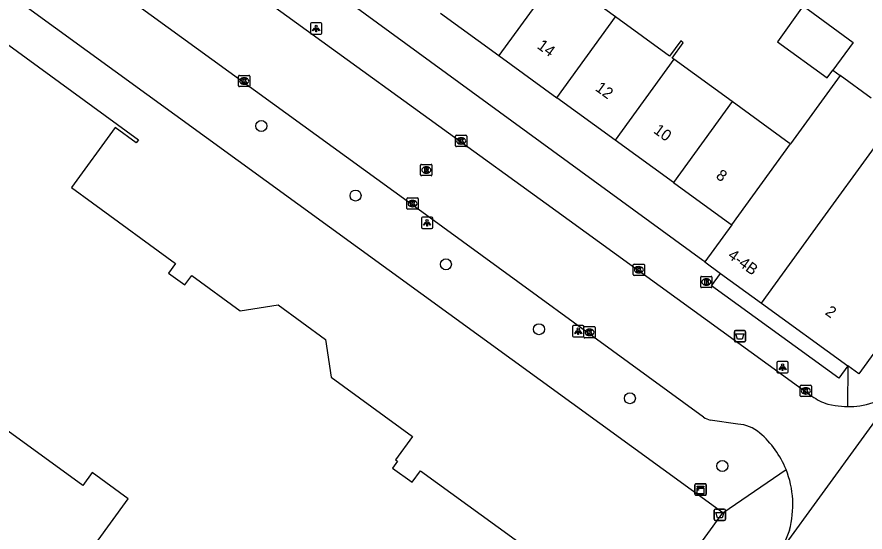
# Model space of a CAD drawing. Extents: x 159675 to 160530, y 382179 to 382901.
# Drawn here: x 160100.6 to 160175.7, y 382438.2 to 382483.9 of the extents above; entities that cross this region are included whole.
import ezdxf

# ---------------------------------------------------------------- set-up
doc = ezdxf.new("R2010")
doc.units = 0
for name, color, linetype in [('IMGEO_Afvalbak', 7, 'Continuous'), ('IMGEO_Boom', 7, 'Continuous'), ('IMGEO_Brandkraan', 7, 'Continuous'), ('IMGEO_Kast', 7, 'Continuous'), ('IMGEO_Kolk', 7, 'Continuous'), ('IMGEO_Lichtpunt', 7, 'Continuous'), ('IMGEO_Pand', 7, 'Continuous'), ('IMGEO_Pand_nummerreeks', 7, 'Continuous'), ('IMGEO_Rijbaan_lokaal_gesloten', 7, 'Continuous'), ('IMGEO_Rijbaan_lokaal_open', 7, 'Continuous'), ('IMGEO_Rioolput', 7, 'Continuous'), ('IMGEO_Voetpad_open', 7, 'Continuous')]:
    doc.layers.add(name, color=color, linetype=linetype)

msp = doc.modelspace()

# ---------------------------------------------------------------- linework, layer by layer
at = {"layer": 'IMGEO_Afvalbak'}
for p, q in [((160164.146, 382455.161), (160164.146, 382455.961)), ((160164.146, 382455.961), (160164.146, 382455.161)), ((160164.246, 382456.061), (160165.036, 382456.061)), ((160165.036, 382456.061), (160164.246, 382456.061)), ((160165.136, 382455.961), (160165.136, 382455.161)), ((160165.136, 382455.161), (160165.136, 382455.961)), ((160165.036, 382455.061), (160164.246, 382455.061)), ((160164.246, 382455.061), (160165.036, 382455.061)), ((160162.369, 382439.328), (160162.369, 382440.128)), ((160162.369, 382440.128), (160162.369, 382439.328)), ((160162.469, 382440.228), (160163.259, 382440.228)), ((160163.259, 382440.228), (160162.469, 382440.228)), ((160163.359, 382440.128), (160163.359, 382439.328)), ((160163.359, 382439.328), (160163.359, 382440.128)), ((160163.259, 382439.228), (160162.469, 382439.228)), ((160162.469, 382439.228), (160163.259, 382439.228))]:
    msp.add_line(p, q, dxfattribs=at)
for points in [[(160164.289, 382455.775), (160164.993, 382455.775), (160164.844, 382455.305), (160164.438, 382455.305), (160164.289, 382455.775)], [(160162.512, 382439.942), (160163.216, 382439.942), (160163.067, 382439.472), (160162.661, 382439.472), (160162.512, 382439.942)]]:
    msp.add_lwpolyline(points, dxfattribs=at)
for centre, start, end in [((160164.246, 382455.961), 90, 180), ((160164.246, 382455.961), 90, 180), ((160165.036, 382455.961), 0, 90), ((160165.036, 382455.961), 360, 90), ((160164.246, 382455.161), 180, 270), ((160164.246, 382455.161), 180, 270), ((160165.036, 382455.161), 270, 0), ((160165.036, 382455.161), 270, 0), ((160162.469, 382440.128), 90, 180), ((160162.469, 382440.128), 90, 180), ((160163.259, 382440.128), 0, 90), ((160163.259, 382440.128), 360, 90), ((160162.469, 382439.328), 180, 270), ((160162.469, 382439.328), 180, 270), ((160163.259, 382439.328), 270, 0), ((160163.259, 382439.328), 270, 0)]:
    msp.add_arc(centre, 0.1, start, end, dxfattribs=at)
at = {"layer": 'IMGEO_Boom'}
for centre in [(160122.222, 382474.208), (160130.572, 382468.037), (160138.58, 382461.94), (160146.827, 382456.187), (160154.885, 382450.065), (160163.082, 382444.058)]:
    msp.add_circle(centre, 0.489, dxfattribs=at)
at = {"layer": 'IMGEO_Brandkraan'}
for p, q in [((160161.163, 382459.947), (160161.163, 382460.799)), ((160161.238, 382460.873), (160162.09, 382460.873)), ((160161.651, 382460.653), (160161.676, 382460.653)), ((160162.164, 382460.799), (160162.164, 382459.947)), ((160162.09, 382459.873), (160161.238, 382459.873)), ((160161.674, 382460.093), (160161.649, 382460.093))]:
    msp.add_line(p, q, dxfattribs=at)
for points in [[(160161.163, 382459.947), (160161.163, 382460.799)], [(160161.238, 382460.873), (160162.09, 382460.873)], [(160161.511, 382460.573), (160161.511, 382460.173), (160161.724, 382460.173)], [(160161.742, 382460.573), (160161.511, 382460.573)], [(160161.69, 382460.492), (160161.636, 382460.492), (160161.636, 382460.416)], [(160161.636, 382460.416), (160161.689, 382460.416)], [(160162.164, 382460.799), (160162.164, 382459.947)], [(160162.09, 382459.873), (160161.238, 382459.873)], [(160161.698, 382460.34), (160161.636, 382460.34), (160161.636, 382460.259)], [(160161.636, 382460.259), (160161.698, 382460.259)]]:
    msp.add_lwpolyline(points, dxfattribs=at)
for centre, radius, start, end in [((160161.24, 382460.797), 0.0765, 91.55205, 178.44795), ((160161.24, 382460.797), 0.0765, 91.55205, 178.44795), ((160161.691, 382460.454), 0.0379, 267.82845, 90.93552), ((160161.746, 382460.428), 0.145, 59.4692, 91.53667), ((160161.771, 382460.475), 0.0922, 285.51372, 58.15012), ((160161.776, 382460.283), 0.105, 301.31148, 78.98903), ((160162.088, 382460.797), 0.0765, 1.55205, 88.44795), ((160162.088, 382460.797), 0.0765, 1.55205, 88.44795), ((160161.24, 382459.949), 0.0765, 181.55205, 268.44795), ((160161.24, 382459.949), 0.0765, 181.55205, 268.44795), ((160161.699, 382460.299), 0.0404, 269.87594, 90.50774), ((160161.73, 382460.424), 0.251, 268.66757, 293.53466), ((160162.088, 382459.949), 0.0765, 271.55205, 358.44795), ((160162.088, 382459.949), 0.0765, 271.55205, 358.44795)]:
    msp.add_arc(centre, radius, start, end, dxfattribs=at)
for centre, major_axis, ratio, start_param, end_param in [((160161.65, 382460.373), (-0.387, 0.002), 0.722429, 4.712389, 7.853982), ((160161.675, 382460.373), (-0.39, 0.002), 0.717154, 1.570796, 4.712389)]:
    msp.add_ellipse(centre, major_axis=major_axis, ratio=ratio, start_param=start_param, end_param=end_param, dxfattribs=at)
at = {"layer": 'IMGEO_Kast'}
for p, q in [((160160.658, 382441.551), (160160.658, 382442.392)), ((160160.658, 382442.392), (160160.658, 382441.551)), ((160160.733, 382442.476), (160161.574, 382442.476)), ((160161.574, 382442.476), (160160.733, 382442.476)), ((160161.658, 382442.401), (160161.658, 382441.56)), ((160161.658, 382441.56), (160161.658, 382442.401)), ((160161.583, 382441.476), (160160.742, 382441.476)), ((160160.742, 382441.476), (160161.583, 382441.476))]:
    msp.add_line(p, q, dxfattribs=at)
for points in [[(160160.853, 382442.266), (160161.453, 382442.266), (160161.453, 382442.181), (160160.853, 382442.181), (160160.853, 382442.266)], [(160160.853, 382442.091), (160161.453, 382442.091), (160161.453, 382441.602), (160160.853, 382441.602), (160160.853, 382442.091)]]:
    msp.add_lwpolyline(points, dxfattribs=at)
msp.add_circle((160160.937, 382441.94), 0.0377, dxfattribs=at)
for centre, start, end in [((160160.736, 382442.398), 92.4484, 184.28452), ((160160.736, 382442.398), 92.4484, 184.28452), ((160161.58, 382442.398), 2.4484, 94.28452), ((160161.58, 382442.398), 2.4484, 94.28452), ((160160.736, 382441.554), 182.4484, 274.28452), ((160160.736, 382441.554), 182.4484, 274.28452), ((160161.58, 382441.554), 272.4484, 4.28452), ((160161.58, 382441.554), 272.4484, 4.28452)]:
    msp.add_arc(centre, 0.0779, start, end, dxfattribs=at)
at = {"layer": 'IMGEO_Kolk'}
for p, q in [((160120.196, 382477.767), (160120.196, 382478.619)), ((160120.271, 382478.693), (160121.123, 382478.693)), ((160120.684, 382478.473), (160120.709, 382478.473)), ((160121.197, 382478.619), (160121.197, 382477.767)), ((160121.123, 382477.693), (160120.271, 382477.693)), ((160120.707, 382477.913), (160120.682, 382477.913)), ((160139.432, 382472.452), (160139.432, 382473.304)), ((160139.507, 382473.378), (160140.359, 382473.378)), ((160140.433, 382473.304), (160140.433, 382472.452)), ((160139.943, 382472.598), (160139.918, 382472.598)), ((160139.92, 382473.158), (160139.945, 382473.158)), ((160140.359, 382472.378), (160139.507, 382472.378)), ((160135.127, 382466.9), (160135.127, 382467.752)), ((160135.202, 382467.826), (160136.054, 382467.826)), ((160135.615, 382467.606), (160135.64, 382467.606)), ((160136.128, 382467.752), (160136.128, 382466.9)), ((160136.054, 382466.826), (160135.202, 382466.826)), ((160135.638, 382467.046), (160135.613, 382467.046)), ((160155.26, 382461.959), (160156.112, 382461.959)), ((160155.185, 382461.033), (160155.185, 382461.885)), ((160155.696, 382461.179), (160155.671, 382461.179)), ((160155.673, 382461.739), (160155.698, 382461.739)), ((160156.186, 382461.885), (160156.186, 382461.033)), ((160156.112, 382460.959), (160155.26, 382460.959)), ((160150.813, 382455.485), (160150.813, 382456.337)), ((160150.888, 382456.411), (160151.74, 382456.411)), ((160151.301, 382456.191), (160151.326, 382456.191)), ((160151.814, 382456.337), (160151.814, 382455.485)), ((160151.74, 382455.411), (160150.888, 382455.411)), ((160151.324, 382455.631), (160151.299, 382455.631)), ((160169.982, 382450.292), (160169.982, 382451.144)), ((160170.057, 382451.218), (160170.909, 382451.218)), ((160170.47, 382450.998), (160170.495, 382450.998)), ((160170.983, 382451.144), (160170.983, 382450.292)), ((160170.909, 382450.218), (160170.057, 382450.218)), ((160170.493, 382450.438), (160170.468, 382450.438))]:
    msp.add_line(p, q, dxfattribs=at)
for points in [[(160120.196, 382477.767), (160120.196, 382478.619)], [(160120.271, 382478.693), (160121.123, 382478.693)], [(160121.197, 382478.619), (160121.197, 382477.767)], [(160121.123, 382477.693), (160120.271, 382477.693)], [(160120.517, 382478.393), (160120.64, 382478.393), (160120.64, 382478.242), (160120.77, 382478.393), (160120.934, 382478.393), (160120.788, 382478.242), (160120.941, 382477.993), (160120.789, 382477.993), (160120.704, 382478.157), (160120.64, 382478.09), (160120.64, 382477.993), (160120.517, 382477.993), (160120.517, 382478.393)], [(160139.432, 382472.452), (160139.432, 382473.304)], [(160139.507, 382473.378), (160140.359, 382473.378)], [(160140.433, 382473.304), (160140.433, 382472.452)], [(160139.753, 382473.078), (160139.876, 382473.078), (160139.876, 382472.927), (160140.006, 382473.078), (160140.17, 382473.078), (160140.024, 382472.927), (160140.177, 382472.678), (160140.025, 382472.678), (160139.94, 382472.842), (160139.876, 382472.775), (160139.876, 382472.678), (160139.753, 382472.678), (160139.753, 382473.078)], [(160140.359, 382472.378), (160139.507, 382472.378)], [(160135.127, 382466.9), (160135.127, 382467.752)], [(160135.202, 382467.826), (160136.054, 382467.826)], [(160135.448, 382467.526), (160135.571, 382467.526), (160135.571, 382467.375), (160135.701, 382467.526), (160135.865, 382467.526), (160135.719, 382467.375), (160135.872, 382467.126), (160135.72, 382467.126), (160135.635, 382467.29), (160135.571, 382467.223), (160135.571, 382467.126), (160135.448, 382467.126), (160135.448, 382467.526)], [(160136.128, 382467.752), (160136.128, 382466.9)], [(160136.054, 382466.826), (160135.202, 382466.826)], [(160155.26, 382461.959), (160156.112, 382461.959)], [(160155.185, 382461.033), (160155.185, 382461.885)], [(160155.506, 382461.659), (160155.629, 382461.659), (160155.629, 382461.508), (160155.759, 382461.659), (160155.923, 382461.659), (160155.777, 382461.508), (160155.93, 382461.259), (160155.778, 382461.259), (160155.693, 382461.423), (160155.629, 382461.356), (160155.629, 382461.259), (160155.506, 382461.259), (160155.506, 382461.659)], [(160156.186, 382461.885), (160156.186, 382461.033)], [(160156.112, 382460.959), (160155.26, 382460.959)], [(160150.813, 382455.485), (160150.813, 382456.337)], [(160150.888, 382456.411), (160151.74, 382456.411)], [(160151.134, 382456.111), (160151.257, 382456.111), (160151.257, 382455.96), (160151.387, 382456.111), (160151.551, 382456.111), (160151.405, 382455.96), (160151.558, 382455.711), (160151.406, 382455.711), (160151.321, 382455.875), (160151.257, 382455.808), (160151.257, 382455.711), (160151.134, 382455.711), (160151.134, 382456.111)], [(160151.814, 382456.337), (160151.814, 382455.485)], [(160151.74, 382455.411), (160150.888, 382455.411)], [(160169.982, 382450.292), (160169.982, 382451.144)], [(160170.057, 382451.218), (160170.909, 382451.218)], [(160170.303, 382450.918), (160170.426, 382450.918), (160170.426, 382450.767), (160170.556, 382450.918), (160170.72, 382450.918), (160170.574, 382450.767), (160170.727, 382450.518), (160170.575, 382450.518), (160170.49, 382450.682), (160170.426, 382450.615), (160170.426, 382450.518), (160170.303, 382450.518), (160170.303, 382450.918)], [(160170.983, 382451.144), (160170.983, 382450.292)], [(160170.909, 382450.218), (160170.057, 382450.218)]]:
    msp.add_lwpolyline(points, dxfattribs=at)
for centre, start, end in [((160120.273, 382478.617), 91.55205, 178.44795), ((160120.273, 382478.617), 91.55205, 178.44795), ((160121.121, 382478.617), 1.55205, 88.44795), ((160121.121, 382478.617), 1.55205, 88.44795), ((160120.273, 382477.769), 181.55205, 268.44795), ((160120.273, 382477.769), 181.55205, 268.44795), ((160121.121, 382477.769), 271.55205, 358.44795), ((160121.121, 382477.769), 271.55205, 358.44795), ((160139.509, 382473.302), 91.55205, 178.44795), ((160139.509, 382473.302), 91.55205, 178.44795), ((160140.357, 382473.302), 1.55205, 88.44795), ((160140.357, 382473.302), 1.55205, 88.44795), ((160139.509, 382472.454), 181.55205, 268.44795), ((160139.509, 382472.454), 181.55205, 268.44795), ((160140.357, 382472.454), 271.55205, 358.44795), ((160140.357, 382472.454), 271.55205, 358.44795), ((160135.204, 382467.75), 91.55205, 178.44795), ((160135.204, 382467.75), 91.55205, 178.44795), ((160136.052, 382467.75), 1.55205, 88.44795), ((160136.052, 382467.75), 1.55205, 88.44795), ((160135.204, 382466.902), 181.55205, 268.44795), ((160135.204, 382466.902), 181.55205, 268.44795), ((160136.052, 382466.902), 271.55205, 358.44795), ((160136.052, 382466.902), 271.55205, 358.44795), ((160155.262, 382461.883), 91.55205, 178.44795), ((160155.262, 382461.883), 91.55205, 178.44795), ((160156.11, 382461.883), 1.55205, 88.44795), ((160156.11, 382461.883), 1.55205, 88.44795), ((160155.262, 382461.035), 181.55205, 268.44795), ((160155.262, 382461.035), 181.55205, 268.44795), ((160156.11, 382461.035), 271.55205, 358.44795), ((160156.11, 382461.035), 271.55205, 358.44795), ((160150.89, 382456.335), 91.55205, 178.44795), ((160150.89, 382456.335), 91.55205, 178.44795), ((160151.738, 382456.335), 1.55205, 88.44795), ((160151.738, 382456.335), 1.55205, 88.44795), ((160150.89, 382455.487), 181.55205, 268.44795), ((160150.89, 382455.487), 181.55205, 268.44795), ((160151.738, 382455.487), 271.55205, 358.44795), ((160151.738, 382455.487), 271.55205, 358.44795), ((160170.059, 382451.142), 91.55205, 178.44795), ((160170.059, 382451.142), 91.55205, 178.44795), ((160170.907, 382451.142), 1.55205, 88.44795), ((160170.907, 382451.142), 1.55205, 88.44795), ((160170.059, 382450.294), 181.55205, 268.44795), ((160170.059, 382450.294), 181.55205, 268.44795), ((160170.907, 382450.294), 271.55205, 358.44795), ((160170.907, 382450.294), 271.55205, 358.44795)]:
    msp.add_arc(centre, 0.0765, start, end, dxfattribs=at)
for centre, major_axis, ratio, start_param, end_param in [((160120.683, 382478.193), (-0.387, 0.002), 0.722429, 4.712389, 7.853982), ((160120.708, 382478.193), (-0.39, 0.002), 0.717154, 1.570796, 4.712389), ((160139.919, 382472.878), (-0.387, 0.002), 0.722429, 4.712389, 7.853982), ((160139.944, 382472.878), (-0.39, 0.002), 0.717154, 1.570796, 4.712389), ((160135.614, 382467.326), (-0.387, 0.002), 0.722429, 4.712389, 7.853982), ((160135.639, 382467.326), (-0.39, 0.002), 0.717154, 1.570796, 4.712389), ((160155.672, 382461.459), (-0.387, 0.002), 0.722429, 4.712389, 7.853982), ((160155.697, 382461.459), (-0.39, 0.002), 0.717154, 1.570796, 4.712389), ((160151.3, 382455.911), (-0.387, 0.002), 0.722429, 4.712389, 7.853982), ((160151.325, 382455.911), (-0.39, 0.002), 0.717154, 1.570796, 4.712389), ((160170.469, 382450.718), (-0.387, 0.002), 0.722429, 4.712389, 7.853982), ((160170.494, 382450.718), (-0.39, 0.002), 0.717154, 1.570796, 4.712389)]:
    msp.add_ellipse(centre, major_axis=major_axis, ratio=ratio, start_param=start_param, end_param=end_param, dxfattribs=at)
at = {"layer": 'IMGEO_Lichtpunt'}
for p, q in [((160126.582, 382483.256), (160126.582, 382482.449)), ((160126.582, 382483.256), (160126.582, 382482.449)), ((160127.484, 382483.351), (160126.676, 382483.351)), ((160127.484, 382483.351), (160126.676, 382483.351)), ((160127.578, 382482.449), (160127.578, 382483.256)), ((160127.578, 382482.449), (160127.578, 382483.256)), ((160126.676, 382482.355), (160127.484, 382482.355)), ((160126.676, 382482.355), (160127.484, 382482.355)), ((160136.412, 382466.027), (160136.412, 382465.22)), ((160136.412, 382466.027), (160136.412, 382465.22)), ((160137.314, 382466.122), (160136.506, 382466.122)), ((160137.314, 382466.122), (160136.506, 382466.122)), ((160137.408, 382465.22), (160137.408, 382466.027)), ((160137.408, 382465.22), (160137.408, 382466.027)), ((160136.506, 382465.126), (160137.314, 382465.126)), ((160136.506, 382465.126), (160137.314, 382465.126)), ((160149.809, 382456.41), (160149.809, 382455.603)), ((160149.809, 382456.41), (160149.809, 382455.603)), ((160150.711, 382456.505), (160149.903, 382456.505)), ((160150.711, 382456.505), (160149.903, 382456.505)), ((160150.805, 382455.603), (160150.805, 382456.41)), ((160150.805, 382455.603), (160150.805, 382456.41)), ((160149.903, 382455.509), (160150.711, 382455.509)), ((160149.903, 382455.509), (160150.711, 382455.509)), ((160167.92, 382453.217), (160167.92, 382452.41)), ((160167.92, 382453.217), (160167.92, 382452.41)), ((160168.822, 382453.312), (160168.014, 382453.312)), ((160168.822, 382453.312), (160168.014, 382453.312)), ((160168.916, 382452.41), (160168.916, 382453.217)), ((160168.916, 382452.41), (160168.916, 382453.217)), ((160168.014, 382452.316), (160168.822, 382452.316)), ((160168.014, 382452.316), (160168.822, 382452.316))]:
    msp.add_line(p, q, dxfattribs=at)
for points in [[(160126.956, 382482.92), (160126.995, 382482.892), (160126.807, 382482.63), (160126.769, 382482.657), (160126.956, 382482.92)], [(160127.058, 382482.872), (160127.105, 382482.872), (160127.105, 382482.55), (160127.058, 382482.55), (160127.058, 382482.872)], [(160127.168, 382482.892), (160127.206, 382482.919), (160127.393, 382482.657), (160127.354, 382482.629), (160127.168, 382482.892)], [(160136.786, 382465.691), (160136.825, 382465.663), (160136.637, 382465.401), (160136.599, 382465.428), (160136.786, 382465.691)], [(160136.998, 382465.663), (160137.036, 382465.69), (160137.223, 382465.428), (160137.184, 382465.4), (160136.998, 382465.663)], [(160136.888, 382465.643), (160136.935, 382465.643), (160136.935, 382465.321), (160136.888, 382465.321), (160136.888, 382465.643)], [(160150.183, 382456.074), (160150.222, 382456.046), (160150.034, 382455.784), (160149.996, 382455.811), (160150.183, 382456.074)], [(160150.285, 382456.026), (160150.332, 382456.026), (160150.332, 382455.704), (160150.285, 382455.704), (160150.285, 382456.026)], [(160150.395, 382456.046), (160150.433, 382456.073), (160150.62, 382455.811), (160150.581, 382455.783), (160150.395, 382456.046)], [(160168.294, 382452.881), (160168.333, 382452.853), (160168.145, 382452.591), (160168.107, 382452.618), (160168.294, 382452.881)], [(160168.506, 382452.853), (160168.544, 382452.88), (160168.731, 382452.618), (160168.692, 382452.59), (160168.506, 382452.853)], [(160168.396, 382452.833), (160168.443, 382452.833), (160168.443, 382452.511), (160168.396, 382452.511), (160168.396, 382452.833)]]:
    msp.add_lwpolyline(points, dxfattribs=at)
for centre in [(160127.081, 382483.054), (160136.911, 382465.825), (160150.308, 382456.208), (160168.419, 382453.015)]:
    msp.add_circle(centre, 0.0994, dxfattribs=at)
for centre, start, end in [((160126.676, 382483.256), 90, 180), ((160126.676, 382483.256), 90, 180), ((160127.484, 382483.256), 0, 90), ((160127.484, 382483.256), 0, 90), ((160126.676, 382482.449), 180, 270), ((160126.676, 382482.449), 180, 270), ((160127.484, 382482.449), 270, 0), ((160127.484, 382482.449), 270, 360), ((160136.506, 382466.027), 90, 180), ((160136.506, 382466.027), 90, 180), ((160137.314, 382466.027), 0, 90), ((160137.314, 382466.027), 0, 90), ((160136.506, 382465.22), 180, 270), ((160136.506, 382465.22), 180, 270), ((160137.314, 382465.22), 270, 0), ((160137.314, 382465.22), 270, 360), ((160149.903, 382456.41), 90, 180), ((160149.903, 382456.41), 90, 180), ((160150.711, 382456.41), 0, 90), ((160150.711, 382456.41), 0, 90), ((160149.903, 382455.603), 180, 270), ((160149.903, 382455.603), 180, 270), ((160150.711, 382455.603), 270, 0), ((160150.711, 382455.603), 270, 360), ((160168.014, 382453.217), 90, 180), ((160168.014, 382453.217), 90, 180), ((160168.822, 382453.217), 0, 90), ((160168.822, 382453.217), 0, 90), ((160168.014, 382452.41), 180, 270), ((160168.014, 382452.41), 180, 270), ((160168.822, 382452.41), 270, 0), ((160168.822, 382452.41), 270, 360)]:
    msp.add_arc(centre, 0.0946, start, end, dxfattribs=at)
at = {"layer": 'IMGEO_Pand'}
for points in [[(160148.464, 382487.621), (160143.26, 382480.459)], [(160153.625, 382483.87), (160148.464, 382487.621)], [(160170.234, 382484.868), (160167.97, 382481.681), (160172.364, 382478.461), (160172.878, 382479.162)], [(160170.234, 382484.868), (160174.675, 382481.615), (160172.878, 382479.162)], [(160096.525, 382483.765), (160111.322, 382472.965), (160111.135, 382472.707), (160109.272, 382474.068), (160105.385, 382468.743), (160107.249, 382467.383), (160114.61, 382462.01), (160113.991, 382461.163), (160115.428, 382460.113), (160116.047, 382460.961), (160120.344, 382457.824), (160123.697, 382458.347), (160127.897, 382455.282), (160128.423, 382451.931), (160135.628, 382446.672), (160134.121, 382444.607), (160134.283, 382444.49), (160133.836, 382443.873), (160135.578, 382442.609), (160136.317, 382443.627), (160150.083, 382433.637)], [(160138.099, 382484.21), (160143.26, 382480.459)], [(160148.42, 382476.709), (160153.625, 382483.87)], [(160158.785, 382480.118), (160158.641, 382480.223), (160159.625, 382481.576), (160159.392, 382481.746), (160158.409, 382480.393), (160153.625, 382483.87)], [(160143.26, 382480.459), (160148.42, 382476.709)], [(160158.785, 382480.118), (160153.582, 382472.958)], [(160163.946, 382476.367), (160158.785, 382480.118)], [(160173.525, 382478.688), (160169.115, 382472.611)], [(160176.28, 382476.685), (160173.525, 382478.688)], [(160153.582, 382472.958), (160148.42, 382476.709)], [(160163.946, 382476.367), (160158.743, 382469.207)], [(160169.115, 382472.611), (160169.012, 382472.685), (160163.946, 382476.367)], [(160166.542, 382458.498), (160171.752, 382465.667), (160176.578, 382472.309), (160178.556, 382475.031)], [(160158.743, 382469.207), (160153.582, 382472.958)], [(160163.916, 382465.448), (160169.115, 382472.611)], [(160158.743, 382469.207), (160163.756, 382465.564), (160163.916, 382465.448)], [(160187.174, 382468.769), (160181.061, 382460.357), (160180.065, 382461.082), (160179.103, 382459.758), (160180.126, 382459.014), (160175.186, 382452.216), (160174.199, 382452.933)], [(160163.916, 382465.448), (160161.521, 382462.147)], [(160161.521, 382462.147), (160162.914, 382461.134)], [(160162.914, 382461.134), (160166.542, 382458.498)], [(160166.542, 382458.498), (160174.199, 382452.933)], [(160099.082, 382425.521), (160110.426, 382441.152), (160107.233, 382443.47), (160106.406, 382442.33), (160098.456, 382448.099), (160096.303, 382445.131)]]:
    msp.add_lwpolyline(points, dxfattribs=at)
at = {"layer": 'IMGEO_Rijbaan_lokaal_gesloten'}
msp.add_lwpolyline([(160179.328, 382451.773), (160168.227, 382436.541)], dxfattribs=at)
at = {"layer": 'IMGEO_Rijbaan_lokaal_open'}
for points in [[(160065.761, 382526.548), (160066.041, 382526.373), (160086.083, 382511.782), (160148.312, 382466.705), (160171.029, 382450.249)], [(160161.419, 382448.379), (160135.135, 382467.543), (160061.99, 382520.627), (160061.728, 382520.822)], [(160172.437, 382449.547), (160173.092, 382449.416)], [(160164.453, 382447.775), (160162.016, 382448.135)], [(160169.029, 382438.37), (160168.691, 382437.473), (160168.227, 382436.541)]]:
    msp.add_lwpolyline(points, dxfattribs=at)
for centre, radius, start, end in [((160174.344, 382455.642), 6.309, 278.41499, 322.18381), ((160173.818, 382454.08), 4.739, 233.94471, 253.05548), ((160174.225, 382456.571), 7.244, 261.00213, 269.63637), ((160174.239, 382456.58), 7.253, 269.52761, 278.14947), ((160162.283, 382449.64), 1.529, 235.59194, 259.94739), ((160164.268, 382444.526), 3.255, 48.97436, 86.73586), ((160160.946, 382440.613), 8.387, 21.93683, 49.4028), ((160160.935, 382440.61), 8.399, 344.52929, 21.92245)]:
    msp.add_arc(centre, radius, start, end, dxfattribs=at)
at = {"layer": 'IMGEO_Rioolput'}
for p, q in [((160136.341, 382469.874), (160136.341, 382470.726)), ((160136.416, 382470.8), (160137.268, 382470.8)), ((160136.829, 382470.58), (160136.854, 382470.58)), ((160137.342, 382470.726), (160137.342, 382469.874)), ((160137.268, 382469.8), (160136.416, 382469.8)), ((160136.852, 382470.02), (160136.827, 382470.02))]:
    msp.add_line(p, q, dxfattribs=at)
for points in [[(160136.341, 382469.874), (160136.341, 382470.726)], [(160136.416, 382470.8), (160137.268, 382470.8)], [(160136.93, 382470.498), (160136.678, 382470.5), (160136.678, 382470.1)], [(160136.678, 382470.1), (160136.802, 382470.1), (160136.802, 382470.262), (160136.813, 382470.262)], [(160136.856, 382470.419), (160136.802, 382470.419), (160136.802, 382470.338)], [(160136.802, 382470.338), (160136.854, 382470.338)], [(160136.86, 382470.233), (160136.931, 382470.1), (160137.071, 382470.1), (160137.006, 382470.226)], [(160137.342, 382470.726), (160137.342, 382469.874)], [(160137.268, 382469.8), (160136.416, 382469.8)]]:
    msp.add_lwpolyline(points, dxfattribs=at)
for centre, radius, start, end in [((160136.418, 382470.724), 0.0765, 91.55205, 178.44795), ((160136.418, 382470.724), 0.0765, 91.55205, 178.44795), ((160136.812, 382470.209), 0.0533, 26.02933, 88.69889), ((160136.838, 382470.527), 0.19, 274.7715, 282.96867), ((160136.862, 382470.323), 0.0964, 77.00612, 93.18647), ((160136.876, 382470.38), 0.0378, 276.66336, 79.67722), ((160136.929, 382470.388), 0.109, 350.36119, 89.41601), ((160136.927, 382470.388), 0.112, 277.58423, 350.98172), ((160136.911, 382470.173), 0.108, 29.51342, 73.79051), ((160137.266, 382470.724), 0.0765, 1.55205, 88.44795), ((160137.266, 382470.724), 0.0765, 1.55205, 88.44795), ((160136.418, 382469.876), 0.0765, 181.55205, 268.44795), ((160136.418, 382469.876), 0.0765, 181.55205, 268.44795), ((160137.266, 382469.876), 0.0765, 271.55205, 358.44795), ((160137.266, 382469.876), 0.0765, 271.55205, 358.44795)]:
    msp.add_arc(centre, radius, start, end, dxfattribs=at)
for centre, major_axis, ratio, start_param, end_param in [((160136.828, 382470.3), (-0.387, 0.002), 0.722429, 4.712389, 7.853982), ((160136.853, 382470.3), (-0.39, 0.002), 0.717154, 1.570796, 4.712389)]:
    msp.add_ellipse(centre, major_axis=major_axis, ratio=ratio, start_param=start_param, end_param=end_param, dxfattribs=at)
at = {"layer": 'IMGEO_Voetpad_open'}
for points in [[(160161.521, 382462.147), (160161.358, 382462.265), (160125.316, 382488.609), (160127.653, 382491.801)], [(160163.121, 382439.912), (160095.853, 382488.776), (160093.109, 382485.042)], [(160172.878, 382479.162), (160173.525, 382478.688)], [(160174.199, 382452.933), (160173.407, 382451.842), (160162.122, 382460.043), (160162.914, 382461.134)], [(160174.199, 382452.933), (160174.179, 382449.327)], [(160163.121, 382439.912), (160168.726, 382443.746)], [(160127.601, 382390.967), (160163.121, 382439.912)]]:
    msp.add_lwpolyline(points, dxfattribs=at)

# ---------------------------------------------------------------- texts
at = {"layer": 'IMGEO_Pand_nummerreeks'}
for s, rotation, p in [('14', 323.99311, (160146.59, 382481.153)), ('12', 323.99311, (160151.746, 382477.406)), ('10', 323.99311, (160156.909, 382473.655)), ('8', 323.99533, (160162.439, 382469.636)), ('4-4B', 324.00106, (160163.495, 382462.566)), ('2', 323.99533, (160172.121, 382457.558))]:
    msp.add_text(s, height=1, rotation=rotation, dxfattribs=at).set_placement(p)

doc.saveas('drawing.dxf')
